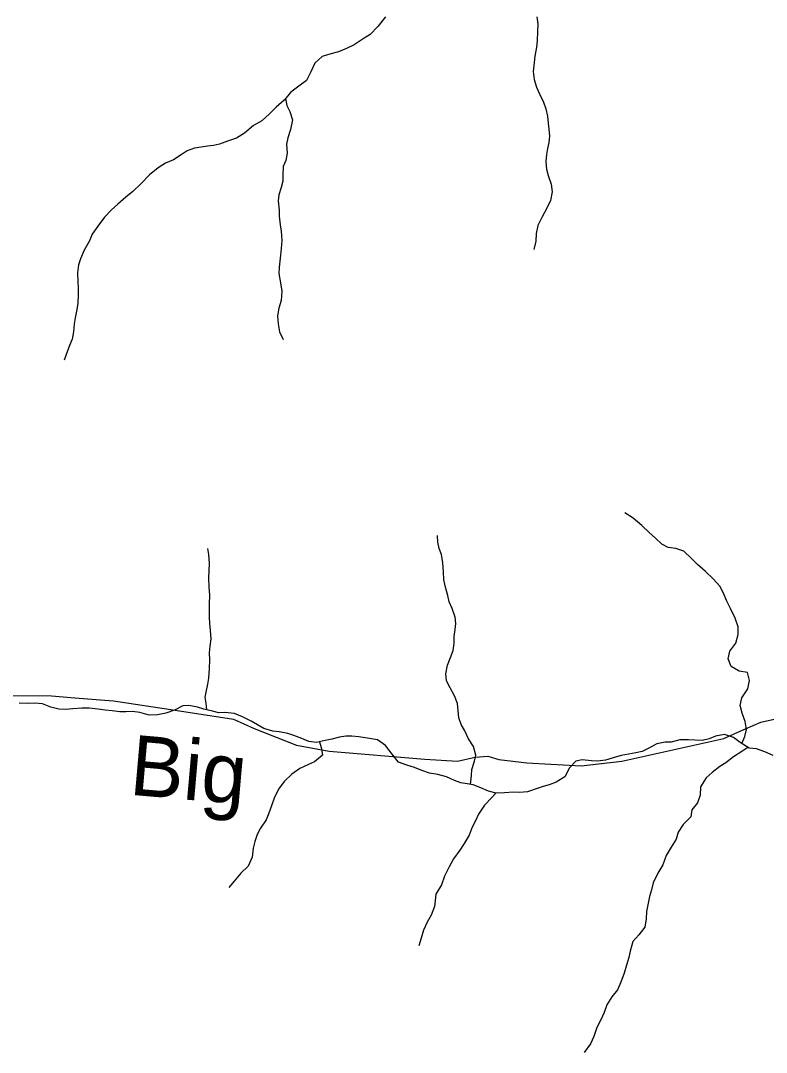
# Model space of a CAD drawing. Extents: x 1624196 to 2029251, y 146837 to 440034.
# Drawn here: x 1804212 to 1810416, y 326837 to 335419 of the extents above; entities that cross this region are included whole.
import ezdxf

# ---------------------------------------------------------------- set-up
doc = ezdxf.new("R2010")
doc.units = 0
for name, color, linetype in [('GM_X_County_Road', 7, 'Continuous'), ('GM_X_Minor_River', 7, 'Continuous'), ('GM_X_Minor_River_Text', 7, 'Continuous')]:
    doc.layers.add(name, color=color, linetype=linetype)

msp = doc.modelspace()

# ---------------------------------------------------------------- linework, layer by layer
at = {"layer": 'GM_X_County_Road'}
for points in [[(1802903.2, 329930), (1803025.7, 329905.8), (1803679.3, 329800), (1804057.6, 329804.8), (1804470, 329801.3), (1804661.5, 329786.2)], [(1804661.5, 329786.2), (1804662.1, 329786.2), (1804984.1, 329760.9), (1805497.8, 329682.3), (1805981.6, 329608.1), (1806155, 329530.5), (1806336.5, 329458.8), (1806508.1, 329393.2), (1806777.8, 329340.8), (1807573.9, 329276), (1807846, 329259.7), (1807992.4, 329292.5), (1808098.5, 329299.6), (1808190.4, 329272.8), (1808422.3, 329244.8), (1808876.5, 329218.9), (1809215.1, 329260.1), (1810061.6, 329447.4), (1810180.1, 329500.5), (1810371.1, 329583.1), (1810704, 329658.4)]]:
    msp.add_lwpolyline(points, dxfattribs=at)
at = {"layer": 'GM_X_Minor_River'}
for points in [[(1807248.9, 335450), (1807184.1, 335370.4), (1807119.5, 335304.8), (1807061.1, 335267.2), (1806986.6, 335217.7), (1806924.2, 335186.1), (1806855.9, 335158.6), (1806791.7, 335143.1), (1806721.5, 335119.6), (1806660.9, 335064), (1806626.2, 334992.1), (1806589.6, 334922.3), (1806525.1, 334872.7), (1806458.6, 334823.2), (1806404, 334757.5), (1806337.4, 334697.9), (1806282.8, 334644.2), (1806218.3, 334586.7), (1806149.9, 334547.1), (1806075.2, 334483.6), (1806006.8, 334440.1), (1805932.5, 334416.6), (1805866.2, 334391.1), (1805816, 334379.5), (1805766, 334373.9), (1805713.8, 334366.3), (1805657.7, 334356.8), (1805597.5, 334337.2), (1805547.1, 334301.6), (1805482.7, 334260), (1805416.4, 334234.5), (1805356, 334194.9), (1805283.4, 334137.4), (1805214.7, 334063.8), (1805144, 333998.2), (1805087.5, 333950.6), (1805021, 333891), (1804964.5, 333841.4), (1804909.9, 333783.7), (1804853.2, 333708), (1804806.6, 333642.3), (1804784.1, 333588.3), (1804739.3, 333510.5), (1804710.7, 333438.6), (1804692.2, 333386.7), (1804683.6, 333320.6)], [(1808506.2, 335451.8), (1808513.7, 335393.6), (1808513.1, 335327.5), (1808508.5, 335251.3), (1808504, 335197.2), (1808491.3, 335123.2), (1808484.9, 335071.2), (1808476.2, 334997.1), (1808483.6, 334928.9), (1808505.1, 334866.6), (1808526.7, 334816.3), (1808562.1, 334741.9), (1808581.6, 334685.6), (1808595.1, 334625.4), (1808600.6, 334567.2), (1808606.1, 334517), (1808611.6, 334458.9), (1808607.2, 334404.8), (1808594.7, 334354.8), (1808586.3, 334304.8), (1808581.8, 334246.7), (1808587.2, 334182.5), (1808600.8, 334130.3), (1808626.2, 334060), (1808633.6, 333993.8), (1808621, 333921.7), (1808588.3, 333853.8), (1808551.7, 333788), (1808515, 333714.1), (1808500.4, 333648.1), (1808497.9, 333584), (1808481.2, 333514)], [(1806416.2, 334772.2), (1806425.6, 334713.2), (1806451.2, 334662.9), (1806472.6, 334592.6), (1806455.9, 334514.6), (1806435.3, 334444.6), (1806422.8, 334390.6), (1806428.1, 334316.4), (1806419.6, 334256.3), (1806395.1, 334204.4), (1806392.5, 334132.3), (1806394.1, 334082.2), (1806379.6, 334030.2), (1806361, 333970.2), (1806354.6, 333920.2), (1806361.9, 333842), (1806363.5, 333791.8), (1806370.9, 333721.6), (1806378.4, 333667.5), (1806385.8, 333591.2), (1806379.2, 333523.1), (1806372.7, 333467.1), (1806368.2, 333417), (1806361.7, 333365), (1806361.3, 333314.9), (1806374.6, 333236.6), (1806384.1, 333168.4), (1806379.4, 333092.2), (1806360.8, 333028.3), (1806350.2, 332964.2), (1806353.6, 332896), (1806365.1, 332829.8), (1806396.5, 332765.4)], [(1804683.6, 333320.6), (1804689, 333248.4), (1804690.5, 333192.3), (1804690, 333138.2), (1804687.4, 333068), (1804679, 333016), (1804664.3, 332946), (1804655.9, 332895.9), (1804651.3, 332829.8), (1804640.8, 332769.8), (1804618.3, 332717.9), (1804597.8, 332663.9), (1804573.2, 332594)], [(1810211.4, 329405.8), (1810237.6, 329463.3), (1810250.2, 329523.3), (1810238.7, 329589.5), (1810215.3, 329657.9), (1810197.8, 329722.2), (1810212.4, 329786.2), (1810261.1, 329859.9), (1810275.7, 329930), (1810258.3, 329996.2), (1810190.3, 330008.8), (1810122.6, 330045.4), (1810099.1, 330109.8), (1810113.7, 330173.8), (1810162.3, 330239.5), (1810183, 330311.5), (1810181.6, 330377.7), (1810158.1, 330448), (1810118.8, 330528.5), (1810087.3, 330590.9), (1810055.9, 330661.3), (1810028.4, 330715.6), (1809972.8, 330776.2), (1809911.3, 330836.8), (1809843.7, 330893.5), (1809794.1, 330946), (1809728.6, 331006.7), (1809662.7, 331027.2), (1809598.7, 331035.8), (1809546.9, 331064.2), (1809493.3, 331114.8), (1809441.7, 331161.3), (1809380.1, 331217.9), (1809308.6, 331280.6), (1809238.9, 331325.3)], [(1807955.9, 329065.1), (1807962.5, 329139), (1807964.9, 329189.1), (1807987.5, 329259.1), (1807998, 329309.1), (1807980.6, 329381.4), (1807937.1, 329445.9), (1807907.7, 329512.3), (1807878.1, 329564.6), (1807856.5, 329618.9), (1807851.1, 329681.1), (1807845.6, 329737.2), (1807822.1, 329801.6), (1807784.7, 329870), (1807755.1, 329928.4), (1807749.7, 329986.5), (1807762.3, 330056.6), (1807788.9, 330120.5), (1807809.4, 330180.5), (1807817.9, 330238.5), (1807818.4, 330294.6), (1807827, 330354.7), (1807833.4, 330404.8), (1807827.8, 330456.9), (1807802.5, 330529.3), (1807776.9, 330585.6), (1807765.4, 330637.8), (1807749.9, 330696), (1807732.5, 330768.3), (1807729, 330834.5), (1807723.7, 330908.7), (1807712.3, 330977), (1807694.7, 331029.2), (1807683.1, 331079.4), (1807679.6, 331135.5)], [(1805760.9, 329685.9), (1805755.5, 329742.2), (1805745.9, 329792.4), (1805758.4, 329846.4), (1805768.9, 329898.5), (1805777.3, 329950.5), (1805784, 330030.6), (1805784.6, 330102.8), (1805783.1, 330158.9), (1805789.6, 330215), (1805796.2, 330277.1), (1805790.8, 330345.2), (1805787.3, 330405.4), (1805783.7, 330455.5), (1805782.2, 330511.7), (1805782.7, 330563.8), (1805785.3, 330639.9), (1805780, 330710.1), (1805776.6, 330780.3), (1805781.1, 330844.4), (1805783.6, 330902.5), (1805776.3, 330976.7), (1805768.7, 331026.9)], [(1806236.1, 329531.9), (1806182.3, 329560.4), (1806130.5, 329590.9), (1806058.8, 329627.5), (1805990.9, 329654.1), (1805911, 329664.8), (1805860.9, 329661.2), (1805806.9, 329673.7), (1805737, 329692.3), (1805683.1, 329706.8), (1805611.1, 329721.4), (1805561.1, 329719.8), (1805492.7, 329682.2), (1805420.4, 329656.8), (1805350.2, 329643.3), (1805280.1, 329641.9), (1805204.2, 329664.6), (1805142.2, 329673.1), (1805086.2, 329669.5), (1805036.1, 329668), (1804972.1, 329676.5), (1804916.1, 329683), (1804856.1, 329691.5), (1804782.1, 329700.1), (1804722, 329700.6), (1804645.9, 329693.2), (1804583.8, 329687.7), (1804529.8, 329690.1), (1804461.8, 329706.7), (1804394, 329735.4), (1804330, 329741.9), (1804273.9, 329738.3), (1804199.8, 329741)], [(1810472.5, 329305), (1810404.7, 329335.7), (1810334.8, 329360.3), (1810272.8, 329366.8), (1810199.1, 329413.5), (1810143.5, 329456), (1810067.6, 329480.7), (1809993.4, 329467.3), (1809939.2, 329445.7), (1809881, 329432.1), (1809820.9, 329434.6), (1809768.9, 329437), (1809696.8, 329437.6), (1809624.6, 329418.2), (1809574.5, 329416.6), (1809506.3, 329403.1), (1809438, 329367.6), (1809383.7, 329339.9), (1809331.5, 329328.3), (1809269.3, 329316.8), (1809207.2, 329307.3), (1809142.9, 329285.8), (1809078.7, 329268.2), (1809012.6, 329258.8), (1808962.5, 329261.2), (1808884.5, 329269.8), (1808830.4, 329258.2), (1808777.9, 329204.5), (1808739.2, 329128.7), (1808666.7, 329083.2), (1808610.4, 329061.6), (1808560.3, 329048), (1808510.1, 329030.3), (1808429.8, 329005), (1808361.6, 328997.5), (1808311.6, 328999.9), (1808237.5, 328994.5), (1808169.4, 328993), (1808105.5, 329009.6), (1808041.6, 329036.2), (1807977.8, 329060.7), (1807925.8, 329071.2), (1807873.8, 329079.6), (1807822, 329098.1), (1807754.2, 329128.7), (1807684.3, 329149.3), (1807614.3, 329159.9), (1807550.4, 329182.5), (1807488.6, 329207), (1807424.7, 329225.6), (1807354.8, 329250.2), (1807303.3, 329316.8), (1807247.9, 329389.3), (1807180.3, 329436), (1807114.3, 329448.6), (1807026.3, 329461.3), (1806968.3, 329465.8), (1806916.3, 329468.2), (1806864.1, 329458.6), (1806799.9, 329443.1), (1806745.8, 329429.5), (1806671.5, 329414.1), (1806609.6, 329422.6), (1806551.7, 329447.1), (1806485.9, 329473.7), (1806433.9, 329488.2), (1806362, 329502.8), (1806310, 329509.2), (1806236.1, 329531.9)], [(1806697.5, 329419.5), (1806711.2, 329371.7), (1806724.7, 329307.4), (1806656.1, 329253.9), (1806605.9, 329232.2), (1806535.5, 329196.7), (1806467, 329151.2), (1806404.4, 329089.6), (1806357.8, 329025.8), (1806321.1, 328949.9), (1806300.6, 328896), (1806278, 328826), (1806255.5, 328772.1), (1806208.8, 328700.3), (1806180.3, 328648.4), (1806159.8, 328590.5), (1806145.3, 328534.5), (1806138.7, 328460.4), (1806106, 328386.5), (1806043.4, 328326.9), (1805988.8, 328261.2), (1805944.3, 328207.4)], [(1810262.8, 329373.2), (1810212.5, 329339.2), (1810142, 329293.7), (1810079.5, 329244.1), (1810029.2, 329214.4), (1809966.7, 329164.8), (1809916.3, 329121.2), (1809869.6, 329045.4), (1809865, 328977.3), (1809844.4, 328911.3), (1809795.8, 328853.6), (1809787.3, 328795.5), (1809724.7, 328731.9), (1809682.1, 328668.1), (1809665.6, 328610.1), (1809622.9, 328544.3), (1809582.3, 328474.5), (1809553.6, 328396.6), (1809512.9, 328326.8), (1809474.2, 328246.9), (1809459.7, 328188.9), (1809445.2, 328132.9), (1809430.5, 328062.8), (1809420.1, 328008.8), (1809415.5, 327948.7), (1809404.9, 327878.7), (1809354.3, 327812.9), (1809305.7, 327759.2), (1809283, 327677.2), (1809272.5, 327625.2), (1809254, 327563.2), (1809233.4, 327495.2), (1809204.7, 327419.3), (1809178.1, 327357.4), (1809131.6, 327299.6), (1809088.9, 327231.8), (1809066.3, 327167.9), (1809039.8, 327108), (1809005.2, 327042.1), (1808980.5, 326968.2), (1808953.9, 326906.2), (1808899.3, 326836.5)], [(1808166.1, 328993.9), (1808133, 328957.2), (1808072.4, 328891.6), (1808021.7, 328817.9), (1807995.2, 328762), (1807968.7, 328710), (1807944.1, 328642.1), (1807901.5, 328574.3), (1807866.9, 328518.5), (1807812.2, 328446.8), (1807777.6, 328380.9), (1807738.9, 328303), (1807712.3, 328231.1), (1807667.5, 328151.3), (1807661.1, 328099.2), (1807654.6, 328049.2), (1807628, 327977.2), (1807593.4, 327919.4), (1807564.8, 327853.5), (1807544.2, 327785.5), (1807523.6, 327723.5)]]:
    msp.add_lwpolyline(points, dxfattribs=at)

# ---------------------------------------------------------------- texts
at = {"layer": 'GM_X_Minor_River_Text'}
msp.add_text('Big', height=499.97, rotation=355.00241, dxfattribs=at).set_placement((1805108, 328980.9))

doc.saveas('drawing.dxf')
